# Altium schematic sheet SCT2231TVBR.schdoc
size 127 x 101 mm
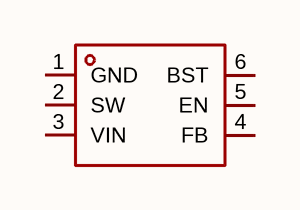
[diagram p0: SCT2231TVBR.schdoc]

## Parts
U?  sct2231tvbr  [TSOT-23-6_L2.9-W1.6-P0.95-LS2.8-BR]  (value not drawn)

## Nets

Not connected (* = marked no-connect by the designer): U? 1(GND) 2(SW) 3(VIN) 4(FB) 5(EN) 6(BST)

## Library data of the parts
U? = sct2231tvbr: 功能类型:降压型;工作电压:4.2V~17V;输出电压:800mV~7V;输出电流:3A;输出类型:可调;; Manufacturer: SCT(芯洲科技); AddInBom: yes; ModelId: 2c4039b5b88644c1bda4b4ba9e971667; ModelName: TSOT-23-6_L2.9-W1.6-H1.1-LS2.8-P0.95; ModelTransform: 110.45568,114.173,0,180,0,0,-0.005,-0.0005,0; Function: 降压型; Output Current: 3A; Frequency - Switching: 750kHz; Synchronous Rectifier: 是; Number of Outputs: 1; Topology: 降压式; Quiescent Current: 275uA; Switch tube (built-in/external): 内置; Output Type: 可调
